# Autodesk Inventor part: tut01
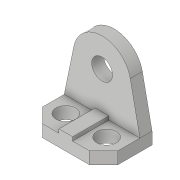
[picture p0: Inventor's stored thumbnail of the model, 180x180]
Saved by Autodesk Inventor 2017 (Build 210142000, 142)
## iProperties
Created: 2015-03
Part Number: tut01
Material: Generic
Document SubType Name: Modeling
Designer: Sandeep
Density: 1 g/cm^3
Appearance: Default
Author: Sandeep
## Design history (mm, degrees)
sketch "Sketch1"
  geometry: L1 (-100, 0)-(100, 0); L2 (100, 0)-(100, -90); L3 (100, -90)-(62, -128); L4 (62, -128)-(-62, -128); L5 (-62, -128)-(-100, -90); L6 (-100, -90)-(-100, 0); L7 (0, 83.092)-(0, -329.034); C1 r 26 at (-54, -74); C2 r 26 at (54, -74); 1 further point
  constraints: 14 end point, 3 perpendicular, 3 point on line, 2 centre point, 1 horizontal, 1 midpoint, 1 parallel, 1 vertical, 3 other
  dimensions: "d0" = 52 diameter of C2; "d1" = 90 distance of L1.end L2.end; "d2" = 124 distance of L3.end L4.end; "d3" = 74 distance from line of C2.centre L1; "d4" = 128 distance between parallel lines of L4 L1; "d5" = 46 distance from line of L2 C2.centre
extrude "Extrusion1" new body sketch "Sketch1" distance "d6" = 32; taper "d7" = 0 deg
sketch "Sketch2"
  geometry: 1 further point
sketch "Sketch3"
  geometry: 1 further point
sketch "Sketch4"
  geometry: L1 (200, -32)-(0, -32) reference; L2 (200, -32)-(174.418, -155.424); L3 (25.582, -155.424)-(0, -32); L4 (200, -32)-(0, -32); L5 (100, 0)-(100, -232.138); L6 (0, 0)-(200, 0) reference; A1 r 76 centre (100, -140) between (25.582, -155.424) and (174.418, -155.424)
  constraints: 8 end point, 2 point on circle, 2 tangent, 1 centre point, 1 collinear, 1 perpendicular, 1 point on line
  dimensions: "d8" = 76 radius of A1; "d9" = 108 distance from line of L1 A1.centre
extrude "Extrusion2" join sketch "Sketch4" distance "d10" = 32; taper "d11" = 0 deg
sketch "Sketch5"
  geometry: L1 (162, 32)-(-38, 32) reference; L2 (44, 32)-(80, 32); L3 (80, 32)-(80, 42); L4 (80, 42)-(44, 42); L5 (44, 42)-(44, 32); L6 (-38, 0)-(-38, 32) reference; 1 further point
  constraints: 8 end point, 2 parallel, 1 horizontal, 1 perpendicular, 1 point on line
  dimensions: "d12" = 10 distance of L4.end L2.start; "d13" = 82 distance between parallel lines of L6 L5; "d14" = 36 distance of L3.end L4.end
extrude "Extrusion3" join sketch "Sketch5" stored distance "d15" = 32; taper "d16" = 0 deg
sketch "Sketch6"
  geometry: C1 r 27.5 at (100, 140); A1 r 76 centre (100, 140) between (174.418, 155.424) and (25.582, 155.424) reference; 1 further point
  constraints: 1 centre point, 1 concentric
  dimensions: "d17" = 55 diameter of C1
extrude "Extrusion4" cut sketch "Sketch6" distance "d18" = 112; taper "d19" = 0 deg
body "Solid1"
